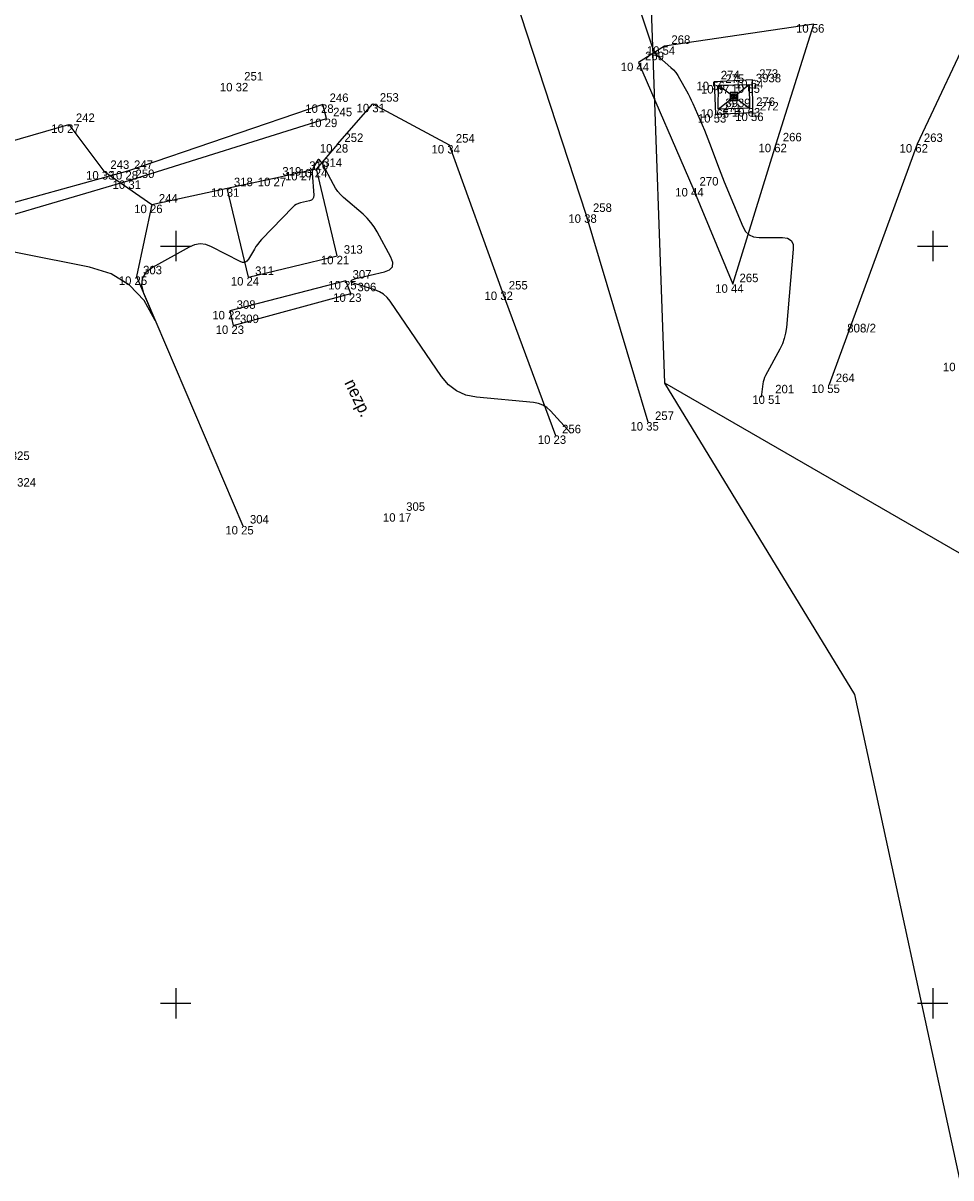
# Model space of a CAD drawing. Extents: x -703403 to -701924, y -1022520 to -1021856.
# Drawn here: x -702305.04 to -702274.4, y -1022305.77 to -1022267.63 of the extents above; entities that cross this region are included whole.
import ezdxf

# ---------------------------------------------------------------- set-up
doc = ezdxf.new("R2010")
doc.units = 0
for name, color, linetype in [('Ex_Minor Contours', 7, 'Continuous'), ('Z_betonova_konstrukce', 7, 'Continuous'), ('Z_body', 7, 'Continuous'), ('Z_body_cisla', 7, 'Continuous'), ('Z_body_vysky_redukovane', 7, 'Continuous'), ('Z_budova', 7, 'Continuous'), ('Z_hektometricka_sit', 7, 'Continuous'), ('Z_katastr_cisla_pozemkova', 7, 'Continuous'), ('Z_katastr_hranice', 7, 'Continuous'), ('Z_komunikace', 7, 'Continuous'), ('Z_komunikace_osa', 7, 'Continuous'), ('Z_popisy', 7, 'Continuous'), ('Z_rozhranni', 7, 'Continuous'), ('Z_sloupy', 7, 'Continuous'), ('Z_svodidla_beton', 7, 'Continuous'), ('Z_vstupy', 7, 'Continuous')]:
    doc.layers.add(name, color=color, linetype=linetype)

# ---------------------------------------------------------------- blocks, each defined once
blk = doc.blocks.new('POINT_DISPLAY')
blk.add_line((0, 0), (0, 0))
blk = doc.blocks.new('Z602')
for p, q in [((0.13, 0.13), (-0.13, 0.13)), ((-0.13, 0.13), (-0.13, -0.13)), ((0.08, 0.08), (-0.08, 0.08)), ((-0.08, 0.08), (-0.08, -0.03)), ((0.03, 0.03), (-0.05, 0.03)), ((0.03, -0.03), (0.03, 0.03)), ((0.08, -0.08), (0.08, 0.08)), ((0.13, -0.13), (0.13, 0.13)), ((-0.13, -0.13), (-0.08, -0.08)), ((-0.13, -0.13), (0.13, -0.13)), ((-0.08, -0.03), (0.03, -0.03)), ((-0.08, -0.08), (0.08, -0.08))]:
    blk.add_line(p, q)

msp = doc.modelspace()

# ---------------------------------------------------------------- linework, layer by layer
at = {"layer": 'Ex_Minor Contours'}
for points in [[(-702284.641, -1022267.298), (-702284.28, -1022268.385), (-702284.236, -1022268.496), (-702284.177, -1022268.598), (-702284.106, -1022268.691), (-702284.021, -1022268.776), (-702283.646, -1022269.102), (-702283.562, -1022269.182), (-702283.486, -1022269.268), (-702283.418, -1022269.36), (-702283.358, -1022269.46), (-702283.133, -1022269.869), (-702283.077, -1022269.972), (-702283.025, -1022270.076), (-702282.975, -1022270.181), (-702282.927, -1022270.287), (-702282.541, -1022271.175), (-702282.482, -1022271.315), (-702282.424, -1022271.455), (-702282.369, -1022271.596), (-702282.316, -1022271.738), (-702282.108, -1022272.308), (-702282.055, -1022272.451), (-702282, -1022272.592), (-702281.944, -1022272.733), (-702281.887, -1022272.874), (-702281.272, -1022274.355), (-702281.183, -1022274.512), (-702281.063, -1022274.624), (-702280.914, -1022274.691), (-702280.735, -1022274.714), (-702279.958, -1022274.716), (-702279.791, -1022274.74), (-702279.676, -1022274.813), (-702279.613, -1022274.934), (-702279.604, -1022275.103), (-702279.832, -1022277.686), (-702279.858, -1022277.873), (-702279.902, -1022278.054), (-702279.965, -1022278.23), (-702280.046, -1022278.401), (-702280.519, -1022279.277), (-702280.551, -1022279.342), (-702280.576, -1022279.41), (-702280.596, -1022279.479), (-702280.609, -1022279.551), (-702280.669, -1022279.985)], [(-702286.95, -1022281.177), (-702287.626, -1022280.44), (-702287.745, -1022280.331), (-702287.878, -1022280.248), (-702288.024, -1022280.192), (-702288.183, -1022280.163), (-702290.068, -1022279.986), (-702290.417, -1022279.917), (-702290.727, -1022279.78), (-702290.996, -1022279.576), (-702291.225, -1022279.303), (-702292.921, -1022276.822), (-702293.023, -1022276.695), (-702293.141, -1022276.591), (-702293.276, -1022276.508), (-702293.427, -1022276.448), (-702294.062, -1022276.249), (-702294.181, -1022276.201), (-702294.22, -1022276.156), (-702294.178, -1022276.113), (-702294.056, -1022276.073), (-702293.111, -1022275.849), (-702292.939, -1022275.782), (-702292.846, -1022275.679), (-702292.831, -1022275.54), (-702292.895, -1022275.367), (-702293.353, -1022274.523), (-702293.449, -1022274.364), (-702293.558, -1022274.215), (-702293.68, -1022274.076), (-702293.815, -1022273.948), (-702294.458, -1022273.391), (-702294.556, -1022273.297), (-702294.645, -1022273.196), (-702294.724, -1022273.087), (-702294.793, -1022272.97), (-702295.158, -1022272.282), (-702295.168, -1022272.264), (-702295.179, -1022272.246), (-702295.191, -1022272.229), (-702295.204, -1022272.213), (-702295.257, -1022272.15), (-702295.27, -1022272.138), (-702295.283, -1022272.135), (-702295.294, -1022272.14), (-702295.305, -1022272.154), (-702295.449, -1022272.392), (-702295.472, -1022272.439), (-702295.488, -1022272.487), (-702295.495, -1022272.537), (-702295.495, -1022272.59), (-702295.441, -1022273.32), (-702295.446, -1022273.389), (-702295.47, -1022273.443), (-702295.515, -1022273.482), (-702295.58, -1022273.505), (-702295.88, -1022273.568), (-702295.952, -1022273.589), (-702296.019, -1022273.62), (-702296.08, -1022273.66), (-702296.136, -1022273.711), (-702297.168, -1022274.785), (-702297.233, -1022274.858), (-702297.294, -1022274.934), (-702297.351, -1022275.013), (-702297.403, -1022275.095), (-702297.601, -1022275.433), (-702297.655, -1022275.501), (-702297.719, -1022275.537), (-702297.791, -1022275.54), (-702297.874, -1022275.511), (-702298.821, -1022275.019), (-702299.008, -1022274.947), (-702299.193, -1022274.925), (-702299.378, -1022274.953), (-702299.563, -1022275.03), (-702300.774, -1022275.706), (-702300.989, -1022275.869), (-702301.109, -1022276.065), (-702301.134, -1022276.293), (-702301.063, -1022276.554), (-702300.68, -1022277.451), (-702301.048, -1022276.797), (-702301.532, -1022276.286), (-702302.132, -1022275.918), (-702302.848, -1022275.694), (-702307.396, -1022274.794)]]:
    msp.add_lwpolyline(points, dxfattribs=at)
at = {"layer": 'Z_betonova_konstrukce'}
for p, q in [((-702280.95, -1022269.51), (-702282.22, -1022269.57)), ((-702282.22, -1022269.57), (-702282.17, -1022270.64)), ((-702280.94, -1022270.59), (-702280.95, -1022269.51)), ((-702282.17, -1022270.64), (-702280.94, -1022270.59))]:
    msp.add_line(p, q, dxfattribs=at)
at = {"layer": 'Z_budova'}
for p, q in [((-702295.81, -1022272.55), (-702295.35, -1022272.45)), ((-702294.67, -1022275.32), (-702295.35, -1022272.45)), ((-702298.3, -1022273.09), (-702296.71, -1022272.74)), ((-702297.6, -1022276.02), (-702298.3, -1022273.09)), ((-702297.6, -1022276.02), (-702294.67, -1022275.32))]:
    msp.add_line(p, q, dxfattribs=at)
at = {"layer": 'Z_hektometricka_sit'}
for p, q in [((-702300, -1022274.5), (-702300, -1022275.5)), ((-702275, -1022274.5), (-702275, -1022275.5)), ((-702300.5, -1022275), (-702299.5, -1022275)), ((-702275.5, -1022275), (-702274.5, -1022275)), ((-702300, -1022299.5), (-702300, -1022300.5)), ((-702275, -1022299.5), (-702275, -1022300.5)), ((-702300.5, -1022300), (-702299.5, -1022300)), ((-702275.5, -1022300), (-702274.5, -1022300))]:
    msp.add_line(p, q, dxfattribs=at)
at = {"layer": 'Z_katastr_hranice'}
for p, q in [((-702283.85, -1022279.53), (-702284.3, -1022266.86)), ((-702271.3, -1022286.77), (-702283.85, -1022279.53)), ((-702277.57, -1022289.81), (-702283.85, -1022279.53)), ((-702247.21, -1022429.7), (-702277.57, -1022289.81))]:
    msp.add_line(p, q, dxfattribs=at)
at = {"layer": 'Z_komunikace'}
for p, q in [((-702278.93, -1022267.67), (-702283.86, -1022268.4)), ((-702280.17, -1022271.62), (-702278.93, -1022267.67)), ((-702283.86, -1022268.4), (-702284.72, -1022268.94)), ((-702284.72, -1022268.94), (-702282.92, -1022273.08)), ((-702294.66, -1022271.63), (-702293.49, -1022270.3)), ((-702293.49, -1022270.3), (-702290.97, -1022271.66)), ((-702306.09, -1022271.72), (-702303.53, -1022270.98)), ((-702303.53, -1022270.98), (-702302.38, -1022272.52)), ((-702294.66, -1022271.63), (-702295.35, -1022272.45)), ((-702290.97, -1022271.66), (-702289.22, -1022276.5)), ((-702281.6, -1022276.26), (-702280.17, -1022271.62)), ((-702302.38, -1022272.52), (-702300.79, -1022273.63)), ((-702300.79, -1022273.63), (-702298.3, -1022273.09)), ((-702282.92, -1022273.08), (-702281.6, -1022276.26)), ((-702289.22, -1022276.5), (-702287.46, -1022281.25))]:
    msp.add_line(p, q, dxfattribs=at)
at = {"layer": 'Z_komunikace_osa'}
for p, q in [((-702272.32, -1022264.84), (-702275.51, -1022271.63)), ((-702286.45, -1022273.95), (-702288.89, -1022266.49)), ((-702275.51, -1022271.63), (-702278.42, -1022279.57)), ((-702284.4, -1022280.81), (-702286.45, -1022273.95))]:
    msp.add_line(p, q, dxfattribs=at)
at = {"layer": 'Z_rozhranni'}
for p, q in [((-702300.79, -1022273.63), (-702301.3, -1022276)), ((-702301.3, -1022276), (-702297.78, -1022284.24))]:
    msp.add_line(p, q, dxfattribs=at)
at = {"layer": 'Z_sloupy'}
for p, q in [((-702282.08, -1022270.48), (-702281.06, -1022269.66)), ((-702282.08, -1022270.48), (-702282.07, -1022269.68)), ((-702282.07, -1022269.68), (-702281.06, -1022269.66)), ((-702282.07, -1022269.68), (-702281.05, -1022270.44)), ((-702281.06, -1022269.66), (-702281.05, -1022270.44)), ((-702281.05, -1022270.44), (-702282.08, -1022270.48))]:
    msp.add_line(p, q, dxfattribs=at)
at = {"layer": 'Z_svodidla_beton'}
for p, q in [((-702295.14, -1022270.32), (-702301.6, -1022272.52)), ((-702295.02, -1022270.79), (-702295.14, -1022270.32)), ((-702301.55, -1022272.83), (-702295.02, -1022270.79)), ((-702301.6, -1022272.52), (-702307.63, -1022274.2)), ((-702307.45, -1022274.57), (-702301.55, -1022272.83)), ((-702294.38, -1022276.15), (-702298.21, -1022277.14)), ((-702294.22, -1022276.56), (-702294.38, -1022276.15)), ((-702298.1, -1022277.62), (-702294.22, -1022276.56)), ((-702298.21, -1022277.14), (-702298.1, -1022277.62))]:
    msp.add_line(p, q, dxfattribs=at)
at = {"layer": 'Z_vstupy'}
msp.add_line((-702296.71, -1022272.74), (-702295.81, -1022272.55), dxfattribs=at)

# ---------------------------------------------------------------- block references
at = {"layer": 'Z_body'}
for p in [(-702278.93, -1022267.67), (-702283.86, -1022268.4), (-702284.72, -1022268.94), (-702297.96, -1022269.61), (-702282.22, -1022269.57), (-702282.07, -1022269.68), (-702281.06, -1022269.66), (-702280.95, -1022269.51), (-702295.14, -1022270.32), (-702293.49, -1022270.3), (-702282.08, -1022270.48), (-702281.05, -1022270.44), (-702295.02, -1022270.79), (-702282.17, -1022270.64), (-702280.94, -1022270.59), (-702303.53, -1022270.98), (-702294.66, -1022271.63), (-702290.97, -1022271.66), (-702280.17, -1022271.62), (-702275.51, -1022271.63), (-702295.35, -1022272.45), (-702302.38, -1022272.52), (-702301.6, -1022272.52), (-702301.55, -1022272.83), (-702296.71, -1022272.74), (-702295.81, -1022272.55), (-702298.3, -1022273.09), (-702282.92, -1022273.08), (-702300.79, -1022273.63), (-702286.45, -1022273.95), (-702294.67, -1022275.32), (-702301.3, -1022276), (-702297.6, -1022276.02), (-702294.38, -1022276.15), (-702281.6, -1022276.26), (-702294.22, -1022276.56), (-702289.22, -1022276.5), (-702298.21, -1022277.14), (-702298.1, -1022277.62), (-702278.42, -1022279.57), (-702280.42, -1022279.93), (-702284.4, -1022280.81), (-702287.46, -1022281.25), (-702292.62, -1022283.82), (-702297.78, -1022284.24)]:
    msp.add_blockref('POINT_DISPLAY', p, dxfattribs=at)
at = {"layer": 'Z_sloupy'}
msp.add_blockref('Z602', (-702281.56, -1022270.06), dxfattribs=at)

# ---------------------------------------------------------------- texts
at = {"layer": 'Z_body_cisla'}
for s, p in [('268', (-702283.63, -1022268.32)), ('269', (-702284.5, -1022268.86)), ('251', (-702297.74, -1022269.53)), ('274', (-702282, -1022269.49)), ('275', (-702281.85, -1022269.61)), ('3938', (-702280.84, -1022269.59)), ('273', (-702280.73, -1022269.44)), ('246', (-702294.92, -1022270.24)), ('253', (-702293.26, -1022270.23)), ('3939', (-702281.85, -1022270.41)), ('276', (-702280.83, -1022270.37)), ('245', (-702294.8, -1022270.71)), ('271', (-702281.95, -1022270.57)), ('272', (-702280.71, -1022270.52)), ('242', (-702303.3, -1022270.9)), ('252', (-702294.43, -1022271.56)), ('254', (-702290.75, -1022271.58)), ('266', (-702279.95, -1022271.54)), ('263', (-702275.29, -1022271.56)), ('314', (-702295.13, -1022272.38)), ('243', (-702302.16, -1022272.45)), ('247', (-702301.38, -1022272.45)), ('250', (-702301.33, -1022272.75)), ('319', (-702296.48, -1022272.67)), ('310', (-702295.59, -1022272.48)), ('318', (-702298.08, -1022273.02)), ('270', (-702282.7, -1022273)), ('244', (-702300.56, -1022273.56)), ('258', (-702286.22, -1022273.87)), ('313', (-702294.45, -1022275.25)), ('303', (-702301.08, -1022275.93)), ('311', (-702297.38, -1022275.95)), ('307', (-702294.16, -1022276.07)), ('265', (-702281.38, -1022276.19)), ('306', (-702294, -1022276.49)), ('255', (-702289, -1022276.43)), ('308', (-702297.99, -1022277.07)), ('309', (-702297.88, -1022277.54)), ('264', (-702278.2, -1022279.49)), ('201', (-702280.2, -1022279.86)), ('257', (-702284.17, -1022280.74)), ('256', (-702287.24, -1022281.18)), ('325', (-702305.45, -1022282.06)), ('324', (-702305.24, -1022282.94)), ('305', (-702292.39, -1022283.74)), ('304', (-702297.55, -1022284.16))]:
    msp.add_text(s, height=0.28, dxfattribs=at).set_placement(p)
at = {"layer": 'Z_body_vysky_redukovane'}
for s, p in [('10 56', (-702279.513, -1022267.95)), ('10 54', (-702284.443, -1022268.68)), ('10 44', (-702285.303, -1022269.22)), ('10 32', (-702298.543, -1022269.89)), ('10 56', (-702282.803, -1022269.85)), ('10 67', (-702282.653, -1022269.96)), ('10 65', (-702281.643, -1022269.94)), ('10 64', (-702281.533, -1022269.79)), ('10 28', (-702295.723, -1022270.6)), ('10 31', (-702294.027, -1022270.58)), ('10 65', (-702282.663, -1022270.76)), ('10 63', (-702281.633, -1022270.72)), ('10 29', (-702295.603, -1022271.07)), ('10 53', (-702282.753, -1022270.92)), ('10 56', (-702281.523, -1022270.87)), ('10 27', (-702304.113, -1022271.26)), ('10 28', (-702295.243, -1022271.91)), ('10 34', (-702291.553, -1022271.94)), ('10 62', (-702280.753, -1022271.9)), ('10 62', (-702276.093, -1022271.91)), ('10 24', (-702295.933, -1022272.73)), ('10 33', (-702302.963, -1022272.8)), ('10 28', (-702302.183, -1022272.8)), ('10 31', (-702302.087, -1022273.11)), ('10 27', (-702297.293, -1022273.02)), ('10 27', (-702296.393, -1022272.83)), ('10 31', (-702298.837, -1022273.37)), ('10 44', (-702283.503, -1022273.36)), ('10 26', (-702301.373, -1022273.91)), ('10 38', (-702287.033, -1022274.23)), ('10 21', (-702295.207, -1022275.6)), ('10 25', (-702301.883, -1022276.28)), ('10 24', (-702298.183, -1022276.3)), ('10 25', (-702294.963, -1022276.43)), ('10 44', (-702282.183, -1022276.54)), ('10 23', (-702294.803, -1022276.84)), ('10 32', (-702289.803, -1022276.78)), ('10 22', (-702298.793, -1022277.42)), ('10 23', (-702298.683, -1022277.9)), ('10 50', (-702274.66, -1022279.13)), ('10 55', (-702279.003, -1022279.85)), ('10 51', (-702280.957, -1022280.21)), ('10 35', (-702284.983, -1022281.09)), ('10 23', (-702288.043, -1022281.53)), ('10 17', (-702293.157, -1022284.1)), ('10 25', (-702298.363, -1022284.52))]:
    msp.add_text(s, height=0.28, dxfattribs=at).set_placement(p)
at = {"layer": 'Z_katastr_cisla_pozemkova'}
msp.add_text('808/2', height=0.285, dxfattribs=at).set_placement((-702277.825, -1022277.85))
at = {"layer": 'Z_popisy'}
msp.add_text('nezp.', height=0.4, rotation=296.1, dxfattribs=at).set_placement((-702294.44, -1022279.51))

doc.saveas('drawing.dxf')
